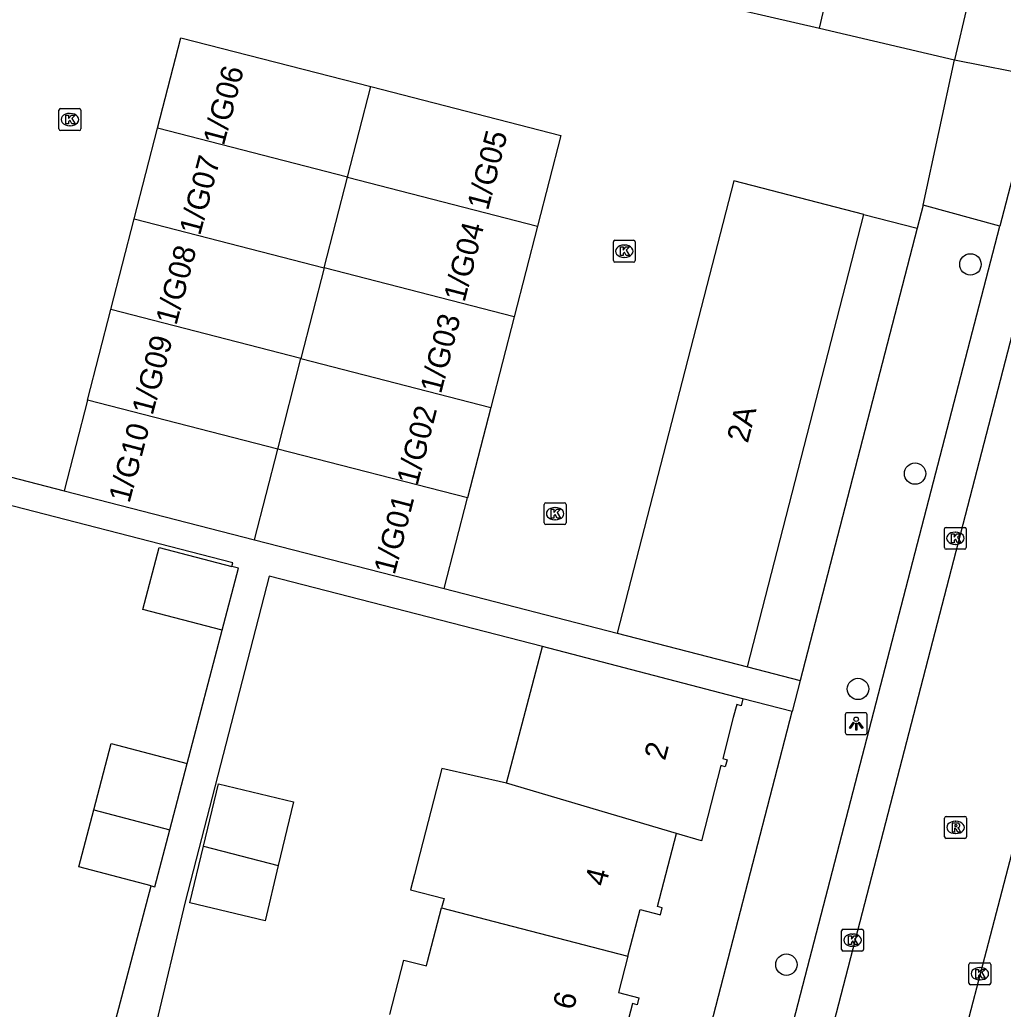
# Model space of a CAD drawing. Extents: x 163686 to 164493, y 382719 to 383870.
# Drawn here: x 163913.6 to 163958.51, y 383236.68 to 383281.87 of the extents above; entities that cross this region are included whole.
import ezdxf

# ---------------------------------------------------------------- set-up
doc = ezdxf.new("R2010")
doc.units = 0
for name, color, linetype in [('IMGEO_Boom', 7, 'Continuous'), ('IMGEO_Kolk', 7, 'Continuous'), ('IMGEO_Lichtpunt', 7, 'Continuous'), ('IMGEO_Muur', 7, 'Continuous'), ('IMGEO_Pand', 7, 'Continuous'), ('IMGEO_Pand_nummerreeks', 7, 'Continuous'), ('IMGEO_Rijbaan_lokaal_open', 7, 'Continuous'), ('IMGEO_Rioolput', 7, 'Continuous'), ('IMGEO_Voetpad_open', 7, 'Continuous')]:
    doc.layers.add(name, color=color, linetype=linetype)

msp = doc.modelspace()

# ---------------------------------------------------------------- linework, layer by layer
at = {"layer": 'IMGEO_Boom'}
for centre in [(163957.014, 383270.698), (163954.485, 383261.146), (163951.878, 383251.311), (163948.61, 383238.72)]:
    msp.add_circle(centre, 0.489, dxfattribs=at)
at = {"layer": 'IMGEO_Kolk'}
for p, q in [((163915.389, 383276.888), (163915.389, 383277.74)), ((163915.464, 383277.814), (163916.316, 383277.814)), ((163915.877, 383277.594), (163915.902, 383277.594)), ((163916.39, 383277.74), (163916.39, 383276.888)), ((163916.316, 383276.814), (163915.464, 383276.814)), ((163915.9, 383277.034), (163915.875, 383277.034)), ((163940.706, 383270.876), (163940.706, 383271.728)), ((163940.781, 383271.802), (163941.633, 383271.802)), ((163941.707, 383271.728), (163941.707, 383270.876)), ((163941.194, 383271.582), (163941.219, 383271.582)), ((163941.633, 383270.802), (163940.781, 383270.802)), ((163941.217, 383271.022), (163941.192, 383271.022)), ((163937.548, 383258.89), (163937.548, 383259.742)), ((163937.623, 383259.816), (163938.475, 383259.816)), ((163938.036, 383259.596), (163938.061, 383259.596)), ((163938.549, 383259.742), (163938.549, 383258.89)), ((163938.059, 383259.036), (163938.034, 383259.036)), ((163938.475, 383258.816), (163937.623, 383258.816)), ((163955.823, 383257.765), (163955.823, 383258.617)), ((163955.898, 383258.691), (163956.75, 383258.691)), ((163956.824, 383258.617), (163956.824, 383257.765)), ((163956.311, 383258.471), (163956.336, 383258.471)), ((163956.75, 383257.691), (163955.898, 383257.691)), ((163956.334, 383257.911), (163956.309, 383257.911)), ((163951.13, 383239.411), (163951.13, 383240.263)), ((163951.205, 383240.337), (163952.057, 383240.337)), ((163951.618, 383240.117), (163951.643, 383240.117)), ((163952.131, 383240.263), (163952.131, 383239.411)), ((163952.057, 383239.337), (163951.205, 383239.337)), ((163951.641, 383239.557), (163951.616, 383239.557)), ((163956.942, 383237.879), (163956.942, 383238.731)), ((163957.017, 383238.805), (163957.869, 383238.805)), ((163957.943, 383238.731), (163957.943, 383237.879)), ((163957.43, 383238.585), (163957.455, 383238.585)), ((163957.869, 383237.805), (163957.017, 383237.805)), ((163957.453, 383238.025), (163957.428, 383238.025))]:
    msp.add_line(p, q, dxfattribs=at)
for points in [[(163915.389, 383276.888), (163915.389, 383277.74)], [(163915.464, 383277.814), (163916.316, 383277.814)], [(163916.39, 383277.74), (163916.39, 383276.888)], [(163915.71, 383277.514), (163915.833, 383277.514), (163915.833, 383277.363), (163915.963, 383277.514), (163916.127, 383277.514), (163915.981, 383277.363), (163916.134, 383277.114), (163915.982, 383277.114), (163915.897, 383277.278), (163915.833, 383277.211), (163915.833, 383277.114), (163915.71, 383277.114), (163915.71, 383277.514)], [(163916.316, 383276.814), (163915.464, 383276.814)], [(163940.706, 383270.876), (163940.706, 383271.728)], [(163940.781, 383271.802), (163941.633, 383271.802)], [(163941.707, 383271.728), (163941.707, 383270.876)], [(163941.027, 383271.502), (163941.15, 383271.502), (163941.15, 383271.351), (163941.28, 383271.502), (163941.444, 383271.502), (163941.298, 383271.351), (163941.451, 383271.102), (163941.299, 383271.102), (163941.214, 383271.266), (163941.15, 383271.199), (163941.15, 383271.102), (163941.027, 383271.102), (163941.027, 383271.502)], [(163941.633, 383270.802), (163940.781, 383270.802)], [(163937.548, 383258.89), (163937.548, 383259.742)], [(163937.623, 383259.816), (163938.475, 383259.816)], [(163937.869, 383259.516), (163937.992, 383259.516), (163937.992, 383259.365), (163938.122, 383259.516), (163938.286, 383259.516), (163938.14, 383259.365), (163938.293, 383259.116), (163938.141, 383259.116), (163938.056, 383259.28), (163937.992, 383259.213), (163937.992, 383259.116), (163937.869, 383259.116), (163937.869, 383259.516)], [(163938.549, 383259.742), (163938.549, 383258.89)], [(163938.475, 383258.816), (163937.623, 383258.816)], [(163955.823, 383257.765), (163955.823, 383258.617)], [(163955.898, 383258.691), (163956.75, 383258.691)], [(163956.824, 383258.617), (163956.824, 383257.765)], [(163956.144, 383258.391), (163956.267, 383258.391), (163956.267, 383258.24), (163956.397, 383258.391), (163956.561, 383258.391), (163956.415, 383258.24), (163956.568, 383257.991), (163956.416, 383257.991), (163956.331, 383258.155), (163956.267, 383258.088), (163956.267, 383257.991), (163956.144, 383257.991), (163956.144, 383258.391)], [(163956.75, 383257.691), (163955.898, 383257.691)], [(163951.13, 383239.411), (163951.13, 383240.263)], [(163951.205, 383240.337), (163952.057, 383240.337)], [(163951.451, 383240.037), (163951.574, 383240.037), (163951.574, 383239.886), (163951.704, 383240.037), (163951.868, 383240.037), (163951.722, 383239.886), (163951.875, 383239.637), (163951.723, 383239.637), (163951.638, 383239.801), (163951.574, 383239.734), (163951.574, 383239.637), (163951.451, 383239.637), (163951.451, 383240.037)], [(163952.131, 383240.263), (163952.131, 383239.411)], [(163952.057, 383239.337), (163951.205, 383239.337)], [(163956.942, 383237.879), (163956.942, 383238.731)], [(163957.017, 383238.805), (163957.869, 383238.805)], [(163957.943, 383238.731), (163957.943, 383237.879)], [(163957.263, 383238.505), (163957.386, 383238.505), (163957.386, 383238.354), (163957.516, 383238.505), (163957.68, 383238.505), (163957.534, 383238.354), (163957.687, 383238.105), (163957.535, 383238.105), (163957.45, 383238.269), (163957.386, 383238.202), (163957.386, 383238.105), (163957.263, 383238.105), (163957.263, 383238.505)], [(163957.869, 383237.805), (163957.017, 383237.805)]]:
    msp.add_lwpolyline(points, dxfattribs=at)
for centre, start, end in [((163915.466, 383277.738), 91.552, 178.448), ((163915.466, 383277.738), 91.552, 178.448), ((163916.314, 383277.738), 1.552, 88.448), ((163916.314, 383277.738), 1.552, 88.448), ((163915.466, 383276.89), 181.552, 268.448), ((163915.466, 383276.89), 181.552, 268.448), ((163916.314, 383276.89), 271.552, 358.448), ((163916.314, 383276.89), 271.552, 358.448), ((163940.783, 383271.726), 91.552, 178.448), ((163940.783, 383271.726), 91.552, 178.448), ((163941.631, 383271.726), 1.552, 88.448), ((163941.631, 383271.726), 1.552, 88.448), ((163940.783, 383270.878), 181.552, 268.448), ((163940.783, 383270.878), 181.552, 268.448), ((163941.631, 383270.878), 271.552, 358.448), ((163941.631, 383270.878), 271.552, 358.448), ((163937.625, 383259.74), 91.552, 178.448), ((163937.625, 383259.74), 91.552, 178.448), ((163938.473, 383259.74), 1.552, 88.448), ((163938.473, 383259.74), 1.552, 88.448), ((163937.625, 383258.892), 181.552, 268.448), ((163937.625, 383258.892), 181.552, 268.448), ((163938.473, 383258.892), 271.552, 358.448), ((163938.473, 383258.892), 271.552, 358.448), ((163955.9, 383258.615), 91.552, 178.448), ((163955.9, 383258.615), 91.552, 178.448), ((163956.748, 383258.615), 1.552, 88.448), ((163956.748, 383258.615), 1.552, 88.448), ((163955.9, 383257.767), 181.552, 268.448), ((163955.9, 383257.767), 181.552, 268.448), ((163956.748, 383257.767), 271.552, 358.448), ((163956.748, 383257.767), 271.552, 358.448), ((163951.207, 383240.261), 91.552, 178.448), ((163951.207, 383240.261), 91.552, 178.448), ((163952.055, 383240.261), 1.552, 88.448), ((163952.055, 383240.261), 1.552, 88.448), ((163951.207, 383239.413), 181.552, 268.448), ((163951.207, 383239.413), 181.552, 268.448), ((163952.055, 383239.413), 271.552, 358.448), ((163952.055, 383239.413), 271.552, 358.448), ((163957.019, 383238.729), 91.552, 178.448), ((163957.019, 383238.729), 91.552, 178.448), ((163957.867, 383238.729), 1.552, 88.448), ((163957.867, 383238.729), 1.552, 88.448), ((163957.019, 383237.881), 181.552, 268.448), ((163957.019, 383237.881), 181.552, 268.448), ((163957.867, 383237.881), 271.552, 358.448), ((163957.867, 383237.881), 271.552, 358.448)]:
    msp.add_arc(centre, 0.0765, start, end, dxfattribs=at)
for centre, major_axis, ratio, start_param, end_param in [((163915.876, 383277.314), (-0.387, 0.002), 0.722429, 4.712389, 7.853982), ((163915.901, 383277.314), (-0.39, 0.002), 0.717154, 1.570796, 4.712389), ((163941.193, 383271.302), (-0.387, 0.002), 0.722429, 4.712389, 7.853982), ((163941.218, 383271.302), (-0.39, 0.002), 0.717154, 1.570796, 4.712389), ((163938.035, 383259.316), (-0.387, 0.002), 0.722429, 4.712389, 7.853982), ((163938.06, 383259.316), (-0.39, 0.002), 0.717154, 1.570796, 4.712389), ((163956.31, 383258.191), (-0.387, 0.002), 0.722429, 4.712389, 7.853982), ((163956.335, 383258.191), (-0.39, 0.002), 0.717154, 1.570796, 4.712389), ((163951.617, 383239.837), (-0.387, 0.002), 0.722429, 4.712389, 7.853982), ((163951.642, 383239.837), (-0.39, 0.002), 0.717154, 1.570796, 4.712389), ((163957.429, 383238.305), (-0.387, 0.002), 0.722429, 4.712389, 7.853982), ((163957.454, 383238.305), (-0.39, 0.002), 0.717154, 1.570796, 4.712389)]:
    msp.add_ellipse(centre, major_axis=major_axis, ratio=ratio, start_param=start_param, end_param=end_param, dxfattribs=at)
at = {"layer": 'IMGEO_Lichtpunt'}
for p, q in [((163951.296, 383250.132), (163951.296, 383249.325)), ((163951.296, 383250.132), (163951.296, 383249.325)), ((163952.198, 383250.227), (163951.39, 383250.227)), ((163952.198, 383250.227), (163951.39, 383250.227)), ((163952.292, 383249.325), (163952.292, 383250.132)), ((163952.292, 383249.325), (163952.292, 383250.132)), ((163951.39, 383249.231), (163952.198, 383249.231)), ((163951.39, 383249.231), (163952.198, 383249.231))]:
    msp.add_line(p, q, dxfattribs=at)
for points in [[(163951.67, 383249.796), (163951.709, 383249.768), (163951.521, 383249.506), (163951.483, 383249.533), (163951.67, 383249.796)], [(163951.772, 383249.748), (163951.819, 383249.748), (163951.819, 383249.426), (163951.772, 383249.426), (163951.772, 383249.748)], [(163951.882, 383249.768), (163951.92, 383249.795), (163952.107, 383249.533), (163952.068, 383249.505), (163951.882, 383249.768)]]:
    msp.add_lwpolyline(points, dxfattribs=at)
msp.add_circle((163951.795, 383249.93), 0.0994, dxfattribs=at)
for centre, start, end in [((163951.39, 383250.132), 90, 180), ((163951.39, 383250.132), 90, 180), ((163952.198, 383250.132), 0, 90), ((163952.198, 383250.132), 0, 90), ((163951.39, 383249.325), 180, 270), ((163951.39, 383249.325), 180, 270), ((163952.198, 383249.325), 270, 0), ((163952.198, 383249.325), 270, 360)]:
    msp.add_arc(centre, 0.0946, start, end, dxfattribs=at)
at = {"layer": 'IMGEO_Muur'}
for points in [[(163907.869, 383262.366), (163915.635, 383260.355)], [(163932.988, 383255.892), (163940.888, 383253.853)]]:
    msp.add_lwpolyline(points, dxfattribs=at)
at = {"layer": 'IMGEO_Pand'}
for points in [[(163950.115, 383281.484), (163954.768, 383301.331)], [(163957.478, 383285.118), (163956.288, 383280.038)], [(163944.283, 383282.849), (163950.115, 383281.484)], [(163950.115, 383281.484), (163956.288, 383280.038)], [(163919.895, 383276.916), (163920.96, 383281.055), (163929.636, 383278.824)], [(163928.572, 383274.684), (163929.636, 383278.824)], [(163929.636, 383278.824), (163938.313, 383276.592), (163937.248, 383272.452)], [(163918.83, 383272.776), (163919.895, 383276.916)], [(163928.572, 383274.684), (163919.895, 383276.916)], [(163927.507, 383270.544), (163928.572, 383274.684)], [(163928.572, 383274.684), (163937.248, 383272.452)], [(163952.14, 383272.983), (163946.201, 383274.51), (163940.888, 383253.853)], [(163917.765, 383268.636), (163918.83, 383272.776)], [(163918.83, 383272.776), (163927.507, 383270.544)], [(163946.827, 383252.325), (163952.14, 383272.983)], [(163937.248, 383272.452), (163936.183, 383268.312)], [(163927.507, 383270.544), (163926.442, 383266.404)], [(163936.183, 383268.312), (163927.507, 383270.544)], [(163916.7, 383264.496), (163917.765, 383268.636)], [(163926.442, 383266.404), (163917.765, 383268.636)], [(163936.183, 383268.312), (163935.118, 383264.172)], [(163925.378, 383262.264), (163926.442, 383266.404)], [(163926.442, 383266.404), (163935.118, 383264.172)], [(163916.7, 383264.496), (163915.635, 383260.355)], [(163925.378, 383262.264), (163916.7, 383264.496)], [(163935.118, 383264.172), (163934.053, 383260.032)], [(163924.313, 383258.123), (163925.378, 383262.264)], [(163934.053, 383260.032), (163925.378, 383262.264)], [(163915.635, 383260.355), (163924.313, 383258.123)], [(163932.988, 383255.892), (163934.053, 383260.032)], [(163924.313, 383258.123), (163932.988, 383255.892)], [(163922.85, 383253.993), (163919.227, 383254.935), (163919.963, 383257.767), (163923.282, 383256.905)], [(163922.85, 383253.993), (163923.586, 383256.826), (163923.282, 383256.905)], [(163940.888, 383253.853), (163946.827, 383252.325)], [(163935.833, 383247.005), (163936.621, 383250), (163937.477, 383253.254)], [(163946.625, 383250.866), (163937.477, 383253.254)], [(163946.625, 383250.866), (163946.542, 383250.547), (163946.339, 383250.601), (163946.184, 383250), (163945.7, 383248.13), (163945.902, 383248.077), (163945.819, 383247.758), (163945.616, 383247.81), (163944.727, 383244.372), (163943.589, 383244.709)], [(163916.982, 383245.783), (163917.776, 383248.814), (163921.249, 383247.903)], [(163920.454, 383244.872), (163921.249, 383247.903)], [(163935.833, 383247.005), (163932.881, 383247.674), (163931.625, 383242.835), (163931.445, 383242.143), (163932.975, 383241.745), (163932.863, 383241.315)], [(163921.99, 383244.134), (163922.669, 383246.973), (163926.102, 383246.153), (163925.407, 383243.248)], [(163943.589, 383244.709), (163935.833, 383247.005)], [(163919.595, 383242.322), (163916.301, 383243.185), (163916.982, 383245.783)], [(163916.982, 383245.783), (163920.454, 383244.872)], [(163919.595, 383242.322), (163919.773, 383242.275), (163920.454, 383244.872)], [(163941.375, 383239.108), (163941.927, 383241.239), (163942.855, 383241), (163942.936, 383241.319), (163942.725, 383241.375), (163943.589, 383244.709)], [(163925.407, 383243.248), (163924.802, 383240.716), (163921.369, 383241.537), (163921.99, 383244.134)], [(163921.99, 383244.134), (163925.407, 383243.248)], [(163930.498, 383236.443), (163931.143, 383238.926), (163932.174, 383238.658), (163932.226, 383238.86), (163932.863, 383241.315)], [(163932.863, 383241.315), (163941.375, 383239.108)], [(163941.375, 383239.108), (163940.946, 383237.45), (163941.872, 383237.209), (163941.79, 383236.89), (163941.578, 383236.945), (163940.659, 383233.398)]]:
    msp.add_lwpolyline(points, dxfattribs=at)
at = {"layer": 'IMGEO_Rijbaan_lokaal_open'}
for points in [[(163967.043, 383298.891), (163932.475, 383165.499)], [(163954.857, 383273.409), (163956.288, 383280.038)], [(163954.857, 383273.409), (163954.582, 383272.35)], [(163952.14, 383272.983), (163954.582, 383272.35)], [(163907.869, 383262.366), (163915.635, 383260.355)], [(163932.988, 383255.892), (163940.888, 383253.853)], [(163947.735, 383201.003), (163959.522, 383246.173)]]:
    msp.add_lwpolyline(points, dxfattribs=at)
at = {"layer": 'IMGEO_Rioolput'}
for p, q in [((163955.909, 383245.488), (163956.761, 383245.488)), ((163955.834, 383244.562), (163955.834, 383245.414)), ((163956.322, 383245.268), (163956.347, 383245.268)), ((163956.835, 383245.414), (163956.835, 383244.562)), ((163956.345, 383244.708), (163956.32, 383244.708)), ((163956.761, 383244.488), (163955.909, 383244.488))]:
    msp.add_line(p, q, dxfattribs=at)
for points in [[(163955.909, 383245.488), (163956.761, 383245.488)], [(163955.834, 383244.562), (163955.834, 383245.414)], [(163956.423, 383245.186), (163956.171, 383245.188), (163956.171, 383244.788)], [(163956.349, 383245.107), (163956.295, 383245.107), (163956.295, 383245.026)], [(163956.295, 383245.026), (163956.347, 383245.026)], [(163956.835, 383245.414), (163956.835, 383244.562)], [(163956.171, 383244.788), (163956.295, 383244.788), (163956.295, 383244.95), (163956.306, 383244.95)], [(163956.353, 383244.921), (163956.424, 383244.788), (163956.564, 383244.788), (163956.499, 383244.914)], [(163956.761, 383244.488), (163955.909, 383244.488)]]:
    msp.add_lwpolyline(points, dxfattribs=at)
for centre, radius, start, end in [((163955.911, 383245.412), 0.0765, 91.552, 178.448), ((163955.911, 383245.412), 0.0765, 91.552, 178.448), ((163956.759, 383245.412), 0.0765, 1.552, 88.448), ((163956.759, 383245.412), 0.0765, 1.552, 88.448), ((163956.331, 383245.215), 0.19, 274.7715, 282.9687), ((163956.355, 383245.011), 0.0964, 77.0061, 93.1865), ((163956.369, 383245.068), 0.0378, 276.6634, 79.6772), ((163956.422, 383245.076), 0.109, 350.3612, 89.416), ((163956.42, 383245.076), 0.112, 277.5842, 350.9817), ((163955.911, 383244.564), 0.0765, 181.552, 268.448), ((163955.911, 383244.564), 0.0765, 181.552, 268.448), ((163956.305, 383244.897), 0.0533, 26.0293, 88.6989), ((163956.404, 383244.861), 0.108, 29.5134, 73.7905), ((163956.759, 383244.564), 0.0765, 271.552, 358.448), ((163956.759, 383244.564), 0.0765, 271.552, 358.448)]:
    msp.add_arc(centre, radius, start, end, dxfattribs=at)
for centre, major_axis, ratio, start_param, end_param in [((163956.321, 383244.988), (-0.387, 0.002), 0.722429, 4.712389, 7.853982), ((163956.346, 383244.988), (-0.39, 0.002), 0.717154, 1.570796, 4.712389)]:
    msp.add_ellipse(centre, major_axis=major_axis, ratio=ratio, start_param=start_param, end_param=end_param, dxfattribs=at)
at = {"layer": 'IMGEO_Voetpad_open'}
for points in [[(163956.288, 383280.038), (163960.14, 383279.284)], [(163960.14, 383279.284), (163958.362, 383272.452)], [(163958.362, 383272.452), (163954.857, 383273.409)], [(163941.824, 383208.725), (163958.362, 383272.452)], [(163954.582, 383272.35), (163949.24, 383251.704)], [(163923.282, 383256.905), (163923.326, 383257.074), (163911.39, 383260.144)], [(163937.477, 383253.254), (163924.986, 383256.466), (163921.16, 383241.587), (163919.768, 383235.768)], [(163921.249, 383247.903), (163922.85, 383253.993)], [(163946.827, 383252.325), (163949.24, 383251.704)], [(163949.24, 383251.704), (163948.873, 383250.284)], [(163948.873, 383250.284), (163946.625, 383250.866)], [(163926.419, 383163.509), (163948.873, 383250.284)], [(163919.768, 383235.768), (163917.993, 383236.216), (163919.595, 383242.322)]]:
    msp.add_lwpolyline(points, dxfattribs=at)

# ---------------------------------------------------------------- texts
at = {"layer": 'IMGEO_Pand_nummerreeks'}
for s, rotation, p in [('1/G06', 75.2135, (163922.916, 383276.088)), ('1/G05', 75.6289, (163934.981, 383273.13)), ('1/G07', 75.2135, (163921.832, 383271.984)), ('1/G04', 75.6289, (163933.908, 383268.942)), ('1/G08', 75.2135, (163920.75, 383267.883)), ('1/G03', 75.6289, (163932.835, 383264.755)), ('1/G09', 75.2135, (163919.665, 383263.773)), ('1/G02', 75.6289, (163931.761, 383260.561)), ('2A', 75.5768, (163946.843, 383262.503)), ('1/G10', 75.2135, (163918.607, 383259.763)), ('1/G01', 75.6289, (163930.717, 383256.487)), ('2', 75.4815, (163943.065, 383248.008)), ('4', 75.4815, (163940.35, 383242.251)), ('6', 75.4815, (163938.888, 383236.606))]:
    msp.add_text(s, height=1, rotation=rotation, dxfattribs=at).set_placement(p)

doc.saveas('drawing.dxf')
